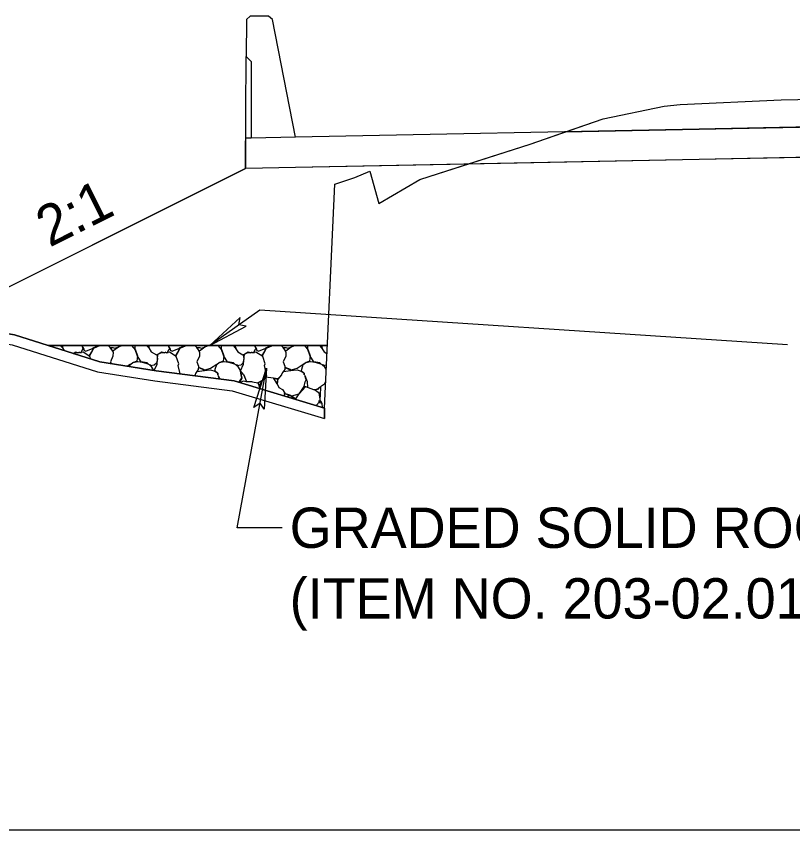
# Model space of a CAD drawing. Extents: x 1574 to 14903, y 7971 to 16537.
# Drawn here: x 14571.09 to 14590.32, y 9500 to 9520.16 of the extents above; entities that cross this region are included whole.
import ezdxf

# ---------------------------------------------------------------- set-up
doc = ezdxf.new("R2010")
doc.units = 0
for name, color, linetype in [('DESIGN - EARTHWORK - Shapes', 7, 'Continuous'), ('DESIGN - SHEET - Light Grid', 7, 'Continuous'), ('DESIGN - SURFACE - Bridge Surface Construction Lines', 7, 'Continuous'), ('DESIGN - TRANSPORTATION - Proposed Layout Patterning', 7, 'Continuous'), ('DESIGN - TYPICAL - Finished Grade and Subgrade', 7, 'Continuous'), ('DESIGN - TYPICAL - Finished Grade Slopes Text', 7, 'Continuous'), ('DESIGN - TYPICAL - Slope Tie Text', 7, 'Continuous'), ('SURVEY - GROUND - Bottom of Topsoil Layer', 7, 'Continuous'), ('SURVEY - GROUND - Top of Ground', 7, 'Continuous')]:
    doc.layers.add(name, color=color, linetype=linetype)

msp = doc.modelspace()

# ---------------------------------------------------------------- linework, layer by layer
at = {"layer": 'DESIGN - EARTHWORK - Shapes'}
for points in [[(14600, 9517.599), (14588, 9517.359), (14584.691, 9517.293), (14585.624, 9517.614), (14587.137, 9517.927), (14587.531, 9517.974), (14590.032, 9518.087), (14600, 9518.286), (14600.862, 9518.31), (14601.961, 9518.332), (14612.445, 9518.188), (14612.873, 9518.174), (14615.194, 9518.114), (14615.777, 9518.069), (14618.285, 9517.549), (14618.847, 9517.222), (14612, 9517.359)], [(14600, 9516.849), (14596, 9516.769), (14588, 9516.609), (14582.265, 9516.494), (14583.814, 9516.991), (14584.691, 9517.293), (14588, 9517.359), (14600, 9517.599), (14612, 9517.359), (14618.847, 9517.222), (14618.884, 9517.2), (14619.463, 9516.959), (14620.287, 9516.65), (14620.886, 9516.483), (14620.972, 9516.429), (14612, 9516.609), (14604, 9516.769)], [(14578, 9516.409), (14576.772, 9516.384), (14576.762, 9516.384), (14569.136, 9512.571), (14571.043, 9512.263), (14573.153, 9511.594), (14574.55, 9511.373), (14576.483, 9511.125), (14578.717, 9510.449), (14578.977, 9516.001), (14579.468, 9516.165), (14579.846, 9516.323), (14580.064, 9515.515), (14581.084, 9516.116), (14582.265, 9516.494)], [(14566.229, 9512.787), (14570.985, 9512.019), (14573.095, 9511.35), (14574.514, 9511.126), (14576.43, 9510.879), (14578.717, 9510.188), (14578.717, 9510.449), (14576.483, 9511.125), (14574.55, 9511.373), (14573.153, 9511.594), (14571.043, 9512.263), (14569.136, 9512.571), (14566.612, 9512.979)]]:
    msp.add_lwpolyline(points, close=True, dxfattribs=at)
at = {"layer": 'DESIGN - SHEET - Light Grid'}
msp.add_line((14300, 9500), (14600, 9500), dxfattribs=at)
at = {"layer": 'DESIGN - SURFACE - Bridge Surface Construction Lines'}
for p, q in [((14576.792, 9520.075), (14576.782, 9519.159)), ((14576.875, 9520.159), (14576.792, 9520.075)), ((14577.333, 9520.159), (14576.875, 9520.159)), ((14577.433, 9520.075), (14577.333, 9520.159)), ((14578, 9517.159), (14577.433, 9520.075)), ((14576.762, 9516.384), (14576.782, 9519.159)), ((14576.782, 9519.159), (14576.907, 9519.034)), ((14576.907, 9519.034), (14576.907, 9517.139))]:
    msp.add_line(p, q, dxfattribs=at)
at = {"layer": 'DESIGN - TRANSPORTATION - Proposed Layout Patterning'}
for p, q in [((14578.79, 9512), (14571.873, 9512)), ((14578.79, 9512), (14571.873, 9512)), ((14571.893, 9511.994), (14571.903, 9512)), ((14571.893, 9511.994), (14571.903, 9512))]:
    msp.add_line(p, q, dxfattribs=at)
for points in [[(14572.175, 9512), (14572.23, 9511.942), (14572.274, 9511.873)], [(14572.175, 9512), (14572.23, 9511.942), (14572.274, 9511.873)], [(14572.223, 9512), (14572.24, 9511.937), (14572.222, 9512)], [(14572.223, 9512), (14572.24, 9511.937), (14572.222, 9512)], [(14572.931, 9511.665), (14572.91, 9511.727), (14572.74, 9511.832), (14572.66, 9511.817), (14572.705, 9511.827), (14572.7, 9511.852), (14572.73, 9511.912), (14572.745, 9511.912), (14572.72, 9511.992), (14572.711, 9512)], [(14572.931, 9511.665), (14572.91, 9511.727), (14572.74, 9511.832), (14572.66, 9511.817), (14572.705, 9511.827), (14572.7, 9511.852), (14572.73, 9511.912), (14572.745, 9511.912), (14572.72, 9511.992), (14572.711, 9512)], [(14572.703, 9512), (14572.71, 9511.992), (14572.755, 9511.912), (14572.76, 9511.882), (14572.805, 9511.857), (14572.99, 9511.937), (14573.159, 9512)], [(14572.703, 9512), (14572.71, 9511.992), (14572.755, 9511.912), (14572.76, 9511.882), (14572.805, 9511.857), (14572.99, 9511.937), (14573.159, 9512)], [(14573.16, 9512), (14572.995, 9511.922), (14572.955, 9511.852), (14572.9, 9511.752), (14572.955, 9511.847), (14572.99, 9511.922), (14572.99, 9511.942), (14573.13, 9512)], [(14573.16, 9512), (14572.995, 9511.922), (14572.955, 9511.852), (14572.9, 9511.752), (14572.955, 9511.847), (14572.99, 9511.922), (14572.99, 9511.942), (14573.13, 9512)], [(14573.365, 9512), (14573.415, 9511.952), (14573.485, 9511.832), (14573.48, 9511.732), (14573.42, 9511.597), (14573.438, 9511.549)], [(14573.365, 9512), (14573.415, 9511.952), (14573.485, 9511.832), (14573.48, 9511.732), (14573.42, 9511.597), (14573.438, 9511.549)], [(14573.676, 9512), (14573.65, 9511.987), (14573.615, 9511.957), (14573.48, 9511.857), (14573.415, 9511.952), (14573.48, 9511.952), (14573.53, 9511.932), (14573.605, 9511.957), (14573.698, 9512)], [(14573.676, 9512), (14573.65, 9511.987), (14573.615, 9511.957), (14573.48, 9511.857), (14573.415, 9511.952), (14573.48, 9511.952), (14573.53, 9511.932), (14573.605, 9511.957), (14573.698, 9512)], [(14573.942, 9512), (14574.035, 9511.887), (14574.085, 9511.742), (14574.07, 9511.612), (14573.985, 9511.582), (14573.915, 9511.532), (14573.975, 9511.582), (14574.095, 9511.602), (14574.205, 9511.587), (14574.32, 9511.552), (14574.405, 9511.517), (14574.487, 9511.383)], [(14573.942, 9512), (14574.035, 9511.887), (14574.085, 9511.742), (14574.07, 9511.612), (14573.985, 9511.582), (14573.915, 9511.532), (14573.975, 9511.582), (14574.095, 9511.602), (14574.205, 9511.587), (14574.32, 9511.552), (14574.405, 9511.517), (14574.487, 9511.383)], [(14574.504, 9511.381), (14574.575, 9511.537), (14574.595, 9511.787), (14574.685, 9511.827), (14574.75, 9511.817), (14574.79, 9511.837), (14574.765, 9511.817), (14574.69, 9511.832), (14574.605, 9511.787), (14574.565, 9511.772), (14574.58, 9511.667), (14574.56, 9511.562), (14574.505, 9511.512), (14574.41, 9511.497), (14574.325, 9511.567), (14574.18, 9511.597), (14574.085, 9511.732), (14574.03, 9511.902), (14574.03, 9511.992), (14574.043, 9512)], [(14574.504, 9511.381), (14574.575, 9511.537), (14574.595, 9511.787), (14574.685, 9511.827), (14574.75, 9511.817), (14574.79, 9511.837), (14574.765, 9511.817), (14574.69, 9511.832), (14574.605, 9511.787), (14574.565, 9511.772), (14574.58, 9511.667), (14574.56, 9511.562), (14574.505, 9511.512), (14574.41, 9511.497), (14574.325, 9511.567), (14574.18, 9511.597), (14574.085, 9511.732), (14574.03, 9511.902), (14574.03, 9511.992), (14574.043, 9512)], [(14574.315, 9512), (14574.37, 9511.942), (14574.43, 9511.847), (14574.555, 9511.772)], [(14574.315, 9512), (14574.37, 9511.942), (14574.43, 9511.847), (14574.555, 9511.772)], [(14574.363, 9512), (14574.38, 9511.937), (14574.362, 9512)], [(14574.363, 9512), (14574.38, 9511.937), (14574.362, 9512)], [(14575.142, 9511.297), (14575.095, 9511.502), (14575.11, 9511.542), (14575.05, 9511.727), (14574.88, 9511.832), (14574.8, 9511.817), (14574.845, 9511.827), (14574.84, 9511.852), (14574.87, 9511.912), (14574.885, 9511.912), (14574.86, 9511.992), (14574.851, 9512)], [(14575.142, 9511.297), (14575.095, 9511.502), (14575.11, 9511.542), (14575.05, 9511.727), (14574.88, 9511.832), (14574.8, 9511.817), (14574.845, 9511.827), (14574.84, 9511.852), (14574.87, 9511.912), (14574.885, 9511.912), (14574.86, 9511.992), (14574.851, 9512)], [(14574.843, 9512), (14574.85, 9511.992), (14574.895, 9511.912), (14574.9, 9511.882), (14574.945, 9511.857), (14575.13, 9511.937), (14575.299, 9512)], [(14574.843, 9512), (14574.85, 9511.992), (14574.895, 9511.912), (14574.9, 9511.882), (14574.945, 9511.857), (14575.13, 9511.937), (14575.299, 9512)], [(14575.3, 9512), (14575.135, 9511.922), (14575.095, 9511.852), (14575.04, 9511.752), (14575.095, 9511.847), (14575.13, 9511.922), (14575.13, 9511.942), (14575.27, 9512)], [(14575.3, 9512), (14575.135, 9511.922), (14575.095, 9511.852), (14575.04, 9511.752), (14575.095, 9511.847), (14575.13, 9511.922), (14575.13, 9511.942), (14575.27, 9512)], [(14575.505, 9512), (14575.555, 9511.952), (14575.625, 9511.832), (14575.62, 9511.732), (14575.56, 9511.597), (14575.6, 9511.487), (14575.595, 9511.402), (14575.525, 9511.307), (14575.515, 9511.277), (14575.56, 9511.352), (14575.745, 9511.377), (14575.735, 9511.402), (14575.605, 9511.452), (14575.75, 9511.392), (14575.815, 9511.392), (14575.9, 9511.397), (14576.005, 9511.362), (14576.075, 9511.312), (14576.08, 9511.277), (14576.075, 9511.307), (14576.01, 9511.367), (14576.015, 9511.417), (14576.05, 9511.527), (14575.9, 9511.432), (14575.75, 9511.392)], [(14575.505, 9512), (14575.555, 9511.952), (14575.625, 9511.832), (14575.62, 9511.732), (14575.56, 9511.597), (14575.6, 9511.487), (14575.595, 9511.402), (14575.525, 9511.307), (14575.515, 9511.277), (14575.56, 9511.352), (14575.745, 9511.377), (14575.735, 9511.402), (14575.605, 9511.452), (14575.75, 9511.392), (14575.815, 9511.392), (14575.9, 9511.397), (14576.005, 9511.362), (14576.075, 9511.312), (14576.08, 9511.277), (14576.075, 9511.307), (14576.01, 9511.367), (14576.015, 9511.417), (14576.05, 9511.527), (14575.9, 9511.432), (14575.75, 9511.392)], [(14575.816, 9512), (14575.79, 9511.987), (14575.755, 9511.957), (14575.62, 9511.857), (14575.555, 9511.952), (14575.62, 9511.952), (14575.67, 9511.932), (14575.745, 9511.957), (14575.838, 9512)], [(14575.816, 9512), (14575.79, 9511.987), (14575.755, 9511.957), (14575.62, 9511.857), (14575.555, 9511.952), (14575.62, 9511.952), (14575.67, 9511.932), (14575.745, 9511.957), (14575.838, 9512)], [(14576.082, 9512), (14576.175, 9511.887), (14576.225, 9511.742), (14576.21, 9511.612), (14576.125, 9511.582), (14576.055, 9511.532), (14576.115, 9511.582), (14576.235, 9511.602), (14576.345, 9511.587), (14576.46, 9511.552), (14576.545, 9511.517), (14576.64, 9511.362), (14576.655, 9511.272), (14576.64, 9511.367), (14576.71, 9511.282), (14576.64, 9511.372), (14576.715, 9511.537), (14576.735, 9511.787), (14576.825, 9511.827), (14576.89, 9511.817), (14576.93, 9511.837), (14576.905, 9511.817), (14576.83, 9511.832), (14576.745, 9511.787), (14576.705, 9511.772), (14576.72, 9511.667), (14576.7, 9511.562), (14576.645, 9511.512), (14576.55, 9511.497), (14576.465, 9511.567), (14576.32, 9511.597), (14576.225, 9511.732), (14576.17, 9511.902), (14576.17, 9511.992), (14576.183, 9512)], [(14576.082, 9512), (14576.175, 9511.887), (14576.225, 9511.742), (14576.21, 9511.612), (14576.125, 9511.582), (14576.055, 9511.532), (14576.115, 9511.582), (14576.235, 9511.602), (14576.345, 9511.587), (14576.46, 9511.552), (14576.545, 9511.517), (14576.64, 9511.362), (14576.655, 9511.272), (14576.64, 9511.367), (14576.71, 9511.282), (14576.64, 9511.372), (14576.715, 9511.537), (14576.735, 9511.787), (14576.825, 9511.827), (14576.89, 9511.817), (14576.93, 9511.837), (14576.905, 9511.817), (14576.83, 9511.832), (14576.745, 9511.787), (14576.705, 9511.772), (14576.72, 9511.667), (14576.7, 9511.562), (14576.645, 9511.512), (14576.55, 9511.497), (14576.465, 9511.567), (14576.32, 9511.597), (14576.225, 9511.732), (14576.17, 9511.902), (14576.17, 9511.992), (14576.183, 9512)], [(14576.455, 9512), (14576.51, 9511.942), (14576.57, 9511.847), (14576.695, 9511.772)], [(14576.455, 9512), (14576.51, 9511.942), (14576.57, 9511.847), (14576.695, 9511.772)], [(14576.503, 9512), (14576.52, 9511.937), (14576.502, 9512)], [(14576.503, 9512), (14576.52, 9511.937), (14576.502, 9512)], [(14577.285, 9511.282), (14577.235, 9511.502), (14577.25, 9511.542), (14577.19, 9511.727), (14577.02, 9511.832), (14576.94, 9511.817), (14576.985, 9511.827), (14576.98, 9511.852), (14577.01, 9511.912), (14577.025, 9511.912), (14577, 9511.992), (14576.991, 9512)], [(14577.285, 9511.282), (14577.235, 9511.502), (14577.25, 9511.542), (14577.19, 9511.727), (14577.02, 9511.832), (14576.94, 9511.817), (14576.985, 9511.827), (14576.98, 9511.852), (14577.01, 9511.912), (14577.025, 9511.912), (14577, 9511.992), (14576.991, 9512)], [(14576.983, 9512), (14576.99, 9511.992), (14577.035, 9511.912), (14577.04, 9511.882), (14577.085, 9511.857), (14577.27, 9511.937), (14577.439, 9512)], [(14576.983, 9512), (14576.99, 9511.992), (14577.035, 9511.912), (14577.04, 9511.882), (14577.085, 9511.857), (14577.27, 9511.937), (14577.439, 9512)], [(14577.44, 9512), (14577.275, 9511.922), (14577.235, 9511.852), (14577.18, 9511.752), (14577.235, 9511.847), (14577.27, 9511.922), (14577.27, 9511.942), (14577.41, 9512)], [(14577.44, 9512), (14577.275, 9511.922), (14577.235, 9511.852), (14577.18, 9511.752), (14577.235, 9511.847), (14577.27, 9511.922), (14577.27, 9511.942), (14577.41, 9512)], [(14577.645, 9512), (14577.695, 9511.952), (14577.765, 9511.832), (14577.76, 9511.732), (14577.7, 9511.597), (14577.74, 9511.487), (14577.735, 9511.402), (14577.665, 9511.307), (14577.655, 9511.277), (14577.7, 9511.352), (14577.885, 9511.377), (14577.875, 9511.402), (14577.745, 9511.452), (14577.89, 9511.392), (14577.955, 9511.392), (14578.04, 9511.397), (14578.145, 9511.362), (14578.215, 9511.312), (14578.22, 9511.277), (14578.215, 9511.307), (14578.15, 9511.367), (14578.155, 9511.417), (14578.19, 9511.527), (14578.04, 9511.432), (14577.89, 9511.392)], [(14577.645, 9512), (14577.695, 9511.952), (14577.765, 9511.832), (14577.76, 9511.732), (14577.7, 9511.597), (14577.74, 9511.487), (14577.735, 9511.402), (14577.665, 9511.307), (14577.655, 9511.277), (14577.7, 9511.352), (14577.885, 9511.377), (14577.875, 9511.402), (14577.745, 9511.452), (14577.89, 9511.392), (14577.955, 9511.392), (14578.04, 9511.397), (14578.145, 9511.362), (14578.215, 9511.312), (14578.22, 9511.277), (14578.215, 9511.307), (14578.15, 9511.367), (14578.155, 9511.417), (14578.19, 9511.527), (14578.04, 9511.432), (14577.89, 9511.392)], [(14577.956, 9512), (14577.93, 9511.987), (14577.895, 9511.957), (14577.76, 9511.857), (14577.695, 9511.952), (14577.76, 9511.952), (14577.81, 9511.932), (14577.885, 9511.957), (14577.978, 9512)], [(14577.956, 9512), (14577.93, 9511.987), (14577.895, 9511.957), (14577.76, 9511.857), (14577.695, 9511.952), (14577.76, 9511.952), (14577.81, 9511.932), (14577.885, 9511.957), (14577.978, 9512)], [(14578.222, 9512), (14578.315, 9511.887), (14578.365, 9511.742), (14578.35, 9511.612), (14578.265, 9511.582), (14578.195, 9511.532), (14578.255, 9511.582), (14578.375, 9511.602), (14578.485, 9511.587), (14578.6, 9511.552), (14578.685, 9511.517), (14578.761, 9511.393)], [(14578.222, 9512), (14578.315, 9511.887), (14578.365, 9511.742), (14578.35, 9511.612), (14578.265, 9511.582), (14578.195, 9511.532), (14578.255, 9511.582), (14578.375, 9511.602), (14578.485, 9511.587), (14578.6, 9511.552), (14578.685, 9511.517), (14578.761, 9511.393)], [(14578.767, 9511.51), (14578.69, 9511.497), (14578.605, 9511.567), (14578.46, 9511.597), (14578.365, 9511.732), (14578.31, 9511.902), (14578.31, 9511.992), (14578.323, 9512)], [(14578.767, 9511.51), (14578.69, 9511.497), (14578.605, 9511.567), (14578.46, 9511.597), (14578.365, 9511.732), (14578.31, 9511.902), (14578.31, 9511.992), (14578.323, 9512)], [(14578.595, 9512), (14578.65, 9511.942), (14578.71, 9511.847), (14578.781, 9511.805)], [(14578.595, 9512), (14578.65, 9511.942), (14578.71, 9511.847), (14578.781, 9511.805)], [(14578.643, 9512), (14578.66, 9511.937), (14578.642, 9512)], [(14578.643, 9512), (14578.66, 9511.937), (14578.642, 9512)], [(14572.492, 9511.804), (14572.545, 9511.827), (14572.61, 9511.817), (14572.65, 9511.837), (14572.625, 9511.817), (14572.55, 9511.832), (14572.494, 9511.803)], [(14572.492, 9511.804), (14572.545, 9511.827), (14572.61, 9511.817), (14572.65, 9511.837), (14572.625, 9511.817), (14572.55, 9511.832), (14572.494, 9511.803)], [(14573.894, 9511.477), (14573.91, 9511.527), (14573.843, 9511.485)], [(14573.894, 9511.477), (14573.91, 9511.527), (14573.843, 9511.485)], [(14575.506, 9511.25), (14575.525, 9511.272), (14575.503, 9511.251)], [(14575.506, 9511.25), (14575.525, 9511.272), (14575.503, 9511.251)], [(14576.123, 9511.171), (14576.09, 9511.257), (14576.128, 9511.17)], [(14576.123, 9511.171), (14576.09, 9511.257), (14576.128, 9511.17)], [(14576.603, 9511.088), (14576.67, 9511.197), (14576.66, 9511.262), (14576.675, 9511.192), (14576.608, 9511.087)], [(14576.603, 9511.088), (14576.67, 9511.197), (14576.66, 9511.262), (14576.675, 9511.192), (14576.608, 9511.087)], [(14576.925, 9511.097), (14576.795, 9511.102), (14576.72, 9511.272), (14576.79, 9511.102), (14576.705, 9511.112), (14576.635, 9511.079)], [(14576.925, 9511.097), (14576.795, 9511.102), (14576.72, 9511.272), (14576.79, 9511.102), (14576.705, 9511.112), (14576.635, 9511.079)], [(14576.94, 9511.097), (14577.07, 9511.072), (14577.105, 9510.997), (14577.195, 9511.142), (14577.065, 9511.072), (14577.23, 9511.162), (14577.275, 9511.217), (14577.28, 9511.262), (14577.27, 9511.227), (14577.445, 9511.197), (14577.54, 9511.052), (14577.575, 9511.172), (14577.445, 9511.192), (14577.575, 9511.167), (14577.665, 9511.272), (14577.565, 9511.172), (14577.55, 9511.052), (14577.59, 9510.957), (14577.68, 9510.912), (14577.74, 9510.817), (14577.712, 9510.753)], [(14576.94, 9511.097), (14577.07, 9511.072), (14577.105, 9510.997), (14577.195, 9511.142), (14577.065, 9511.072), (14577.23, 9511.162), (14577.275, 9511.217), (14577.28, 9511.262), (14577.27, 9511.227), (14577.445, 9511.197), (14577.54, 9511.052), (14577.575, 9511.172), (14577.445, 9511.192), (14577.575, 9511.167), (14577.665, 9511.272), (14577.565, 9511.172), (14577.55, 9511.052), (14577.59, 9510.957), (14577.68, 9510.912), (14577.74, 9510.817), (14577.712, 9510.753)], [(14578.671, 9510.463), (14578.66, 9510.562), (14578.59, 9510.582), (14578.59, 9510.637), (14578.63, 9510.622), (14578.655, 9510.562), (14578.625, 9510.622), (14578.59, 9510.822), (14578.47, 9510.902), (14578.55, 9510.922), (14578.6, 9510.962), (14578.625, 9510.957), (14578.59, 9510.957), (14578.55, 9510.912), (14578.46, 9510.902), (14578.255, 9510.972), (14578.22, 9510.987), (14578.24, 9511.102), (14578.27, 9511.152), (14578.23, 9511.257), (14578.295, 9511.107), (14578.3, 9510.962)], [(14578.671, 9510.463), (14578.66, 9510.562), (14578.59, 9510.582), (14578.59, 9510.637), (14578.63, 9510.622), (14578.655, 9510.562), (14578.625, 9510.622), (14578.59, 9510.822), (14578.47, 9510.902), (14578.55, 9510.922), (14578.6, 9510.962), (14578.625, 9510.957), (14578.59, 9510.957), (14578.55, 9510.912), (14578.46, 9510.902), (14578.255, 9510.972), (14578.22, 9510.987), (14578.24, 9511.102), (14578.27, 9511.152), (14578.23, 9511.257), (14578.295, 9511.107), (14578.3, 9510.962)], [(14577.138, 9510.926), (14577.13, 9510.942), (14577.1, 9511.002), (14577.13, 9510.937), (14577.129, 9510.929)], [(14577.138, 9510.926), (14577.13, 9510.942), (14577.1, 9511.002), (14577.13, 9510.937), (14577.129, 9510.929)], [(14577.771, 9510.735), (14577.865, 9510.757), (14577.87, 9510.767), (14577.725, 9510.812), (14577.915, 9510.752), (14578.095, 9510.802), (14578.25, 9510.977), (14578.21, 9510.987), (14578, 9510.677), (14577.88, 9510.762), (14578, 9510.672), (14578.004, 9510.665)], [(14577.771, 9510.735), (14577.865, 9510.757), (14577.87, 9510.767), (14577.725, 9510.812), (14577.915, 9510.752), (14578.095, 9510.802), (14578.25, 9510.977), (14578.21, 9510.987), (14578, 9510.677), (14577.88, 9510.762), (14578, 9510.672), (14578.004, 9510.665)], [(14578.747, 9511.085), (14578.72, 9511.042), (14578.625, 9510.972), (14578.61, 9510.762), (14578.595, 9510.602), (14578.513, 9510.511)], [(14578.747, 9511.085), (14578.72, 9511.042), (14578.625, 9510.972), (14578.61, 9510.762), (14578.595, 9510.602), (14578.513, 9510.511)], [(14578.746, 9511.065), (14578.72, 9511.052), (14578.748, 9511.096)], [(14578.746, 9511.065), (14578.72, 9511.052), (14578.748, 9511.096)]]:
    msp.add_lwpolyline(points, dxfattribs=at)
at = {"layer": 'DESIGN - TYPICAL - Finished Grade and Subgrade'}
for p, q in [((14600, 9517.599), (14588, 9517.359)), ((14588, 9517.359), (14578, 9517.159)), ((14576.767, 9517.136), (14576.762, 9516.384)), ((14576.907, 9517.139), (14576.767, 9517.136)), ((14578, 9517.159), (14576.907, 9517.139)), ((14588, 9516.609), (14578, 9516.409)), ((14596, 9516.769), (14588, 9516.609)), ((14569.136, 9512.571), (14576.762, 9516.384)), ((14576.772, 9516.384), (14576.762, 9516.384)), ((14578, 9516.409), (14576.772, 9516.384)), ((14571.873, 9512), (14578.79, 9512))]:
    msp.add_line(p, q, dxfattribs=at)
at = {"layer": 'DESIGN - TYPICAL - Slope Tie Text'}
for points in [[(14590.186, 9512.016), (14577.115, 9512.878), (14575.881, 9512)], [(14575.881, 9512), (14576.779, 9512.48), (14576.598, 9512.51), (14576.628, 9512.692), (14575.881, 9512)], [(14577.672, 9507.485), (14576.561, 9507.485), (14577.281, 9511.437)], [(14577.281, 9511.437), (14577.228, 9510.42), (14577.123, 9510.572), (14576.972, 9510.467), (14577.281, 9511.437)]]:
    msp.add_lwpolyline(points, dxfattribs=at)
for points in [[(14575.881, 9512), (14576.779, 9512.48), (14576.598, 9512.51), (14576.628, 9512.692)], [(14577.281, 9511.437), (14577.228, 9510.42), (14577.123, 9510.572), (14576.972, 9510.467)]]:
    msp.add_lwpolyline(points, close=True, dxfattribs=at)
at = {"layer": 'SURVEY - GROUND - Bottom of Topsoil Layer'}
msp.add_line((14578.717, 9510.449), (14578.717, 9510.188), dxfattribs=at)
msp.add_lwpolyline([(14462.56, 9507.304), (14463.978, 9507.347), (14475.849, 9509.902), (14478.832, 9510.183), (14487.109, 9511.465), (14492.996, 9512.491), (14505.193, 9514.091), (14507.059, 9514.219), (14507.663, 9514.229), (14508.116, 9514.233), (14533.011, 9514.785), (14534.372, 9514.814), (14538.123, 9514.885), (14553.593, 9514.776), (14556.908, 9513.718), (14560.02, 9513.571), (14562.883, 9513.339), (14564.666, 9513.04), (14570.985, 9512.019), (14573.095, 9511.35), (14574.514, 9511.126), (14576.43, 9510.879), (14578.717, 9510.188)], dxfattribs=at)
at = {"layer": 'SURVEY - GROUND - Top of Ground'}
msp.add_lwpolyline([(14571.043, 9512.263), (14573.153, 9511.594), (14574.55, 9511.373), (14576.483, 9511.125), (14578.717, 9510.449), (14578.977, 9516.001), (14579.468, 9516.165), (14579.846, 9516.323), (14580.064, 9515.515), (14581.084, 9516.116), (14583.814, 9516.991), (14585.624, 9517.614), (14587.137, 9517.927), (14587.531, 9517.974), (14590.032, 9518.087), (14600, 9518.286), (14600.862, 9518.31), (14601.961, 9518.332), (14612.445, 9518.188)], dxfattribs=at)
msp.add_lwpolyline([(14571.043, 9512.263), (14573.153, 9511.594), (14574.55, 9511.373), (14576.483, 9511.125), (14578.717, 9510.449), (14578.977, 9516.001), (14579.468, 9516.165), (14579.846, 9516.323), (14580.064, 9515.515), (14581.084, 9516.116), (14583.814, 9516.991), (14585.624, 9517.614), (14587.137, 9517.927), (14587.531, 9517.974), (14590.032, 9518.087), (14600, 9518.286), (14600.862, 9518.31), (14601.961, 9518.332), (14612.445, 9518.188)], dxfattribs=at)

# ---------------------------------------------------------------- texts
at = {"layer": 'DESIGN - TYPICAL - Finished Grade Slopes Text'}
msp.add_text('2:1', height=1, rotation=26.5959, dxfattribs=at).set_placement((14571.909, 9514.423))
at = {"layer": 'DESIGN - TYPICAL - Slope Tie Text'}
for s, p in [('GRADED SOLID ROCK', (14577.858, 9506.984)), ('(ITEM NO. 203-02.01)', (14577.858, 9505.234))]:
    msp.add_text(s, height=1, rotation=360, dxfattribs=at).set_placement(p)

doc.saveas('drawing.dxf')
